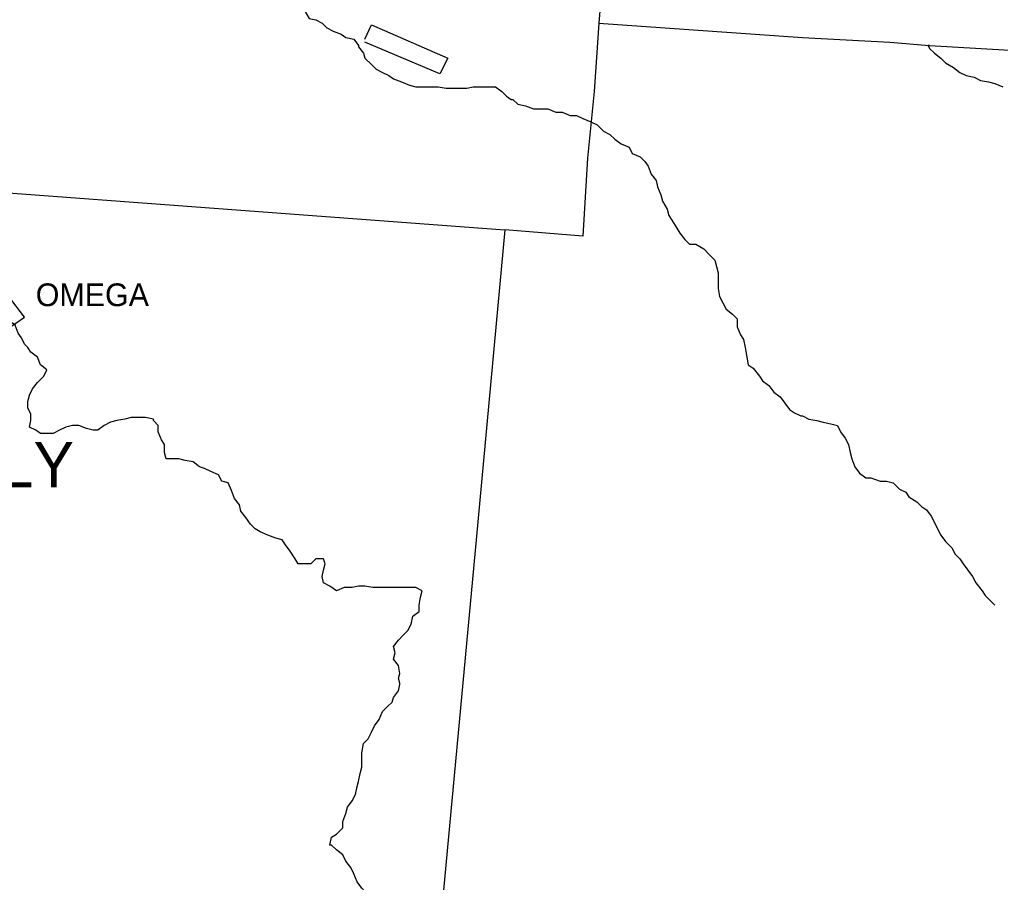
# Model space of a CAD drawing. Extents: x 0 to 34, y 0 to 22.
# Drawn here: x 6.387 to 7.227, y 17.766 to 18.506 of the extents above; entities that cross this region are included whole.
import ezdxf

# ---------------------------------------------------------------- set-up
doc = ezdxf.new("R2010")
doc.units = 0
doc.layers.add('Default', color=7, linetype='Continuous')

msp = doc.modelspace()

# ---------------------------------------------------------------- linework, layer by layer
at = {"layer": 'Default'}
for points in [[(6.94709, 19.42727), (6.93619, 19.25821), (6.91028, 18.871), (6.89937, 18.6992), (6.88301, 18.50287)], [(6.59533, 18.5465), (6.59942, 18.54105), (6.60487, 18.53832), (6.60897, 18.5315), (6.61169, 18.52741), (6.61715, 18.52741), (6.62124, 18.5206), (6.62533, 18.51651), (6.63078, 18.51378), (6.63487, 18.50696), (6.64032, 18.5056), (6.64578, 18.50287), (6.64987, 18.49878), (6.65532, 18.49605), (6.66214, 18.49333), (6.66623, 18.4906), (6.67305, 18.48924), (6.67714, 18.48378), (6.67714, 18.48242)], [(6.68259, 18.48924), (6.68804, 18.50151), (6.75349, 18.47288), (6.74667, 18.45924), (6.68259, 18.48651)], [(6.88301, 18.50287), (6.88301, 18.50287), (6.87892, 18.44424), (6.87347, 18.38698), (6.86938, 18.32017), (6.80257, 18.32563)], [(6.88301, 18.50287), (7.05753, 18.4906), (7.13252, 18.48651), (7.1666, 18.48378), (7.27977, 18.47697), (7.27431, 18.4197), (7.31249, 18.41561), (7.35339, 18.4088), (7.40929, 18.40062), (7.44065, 18.39925), (7.49792, 18.39925), (7.55109, 18.39925), (7.60017, 18.39107), (7.67925, 18.38016), (7.66698, 18.21383)], [(6.67714, 18.48242), (6.68123, 18.47697), (6.68259, 18.47288), (6.68804, 18.46742), (6.69213, 18.46333), (6.69759, 18.46061), (6.70304, 18.45788), (6.70713, 18.45515), (6.71395, 18.45243), (6.72077, 18.4497), (6.72622, 18.44833), (6.73167, 18.44833), (6.73849, 18.44833), (6.74531, 18.44833), (6.75212, 18.44697), (6.75621, 18.44697), (6.76303, 18.44697), (6.76985, 18.44697), (6.7753, 18.44833), (6.78076, 18.44833), (6.78894, 18.44833), (6.79439, 18.44833), (6.79984, 18.44424), (6.80393, 18.44015), (6.80802, 18.43743), (6.80939, 18.43743)], [(7.1666, 18.48378), (7.16524, 18.48378), (7.1666, 18.48106), (7.17069, 18.47697), (7.17615, 18.47288), (7.18024, 18.46879), (7.18706, 18.4647), (7.19251, 18.46061), (7.19796, 18.45788), (7.20478, 18.45652), (7.21023, 18.45379), (7.21705, 18.45243), (7.2225, 18.45106), (7.22932, 18.44833)], [(4.80243, 18.46879), (4.94014, 18.46061), (5.51141, 18.4197), (6.14268, 18.37471), (6.80257, 18.32563)], [(6.80939, 18.43743), (6.81348, 18.43334), (6.8203, 18.43197), (6.82711, 18.42925), (6.83257, 18.42925), (6.83938, 18.42925), (6.8462, 18.42652), (6.85165, 18.42652), (6.85847, 18.42379), (6.86392, 18.42379), (6.86938, 18.42107), (6.8762, 18.41834), (6.8762, 18.41834)], [(6.8762, 18.41834), (6.88165, 18.41561), (6.8871, 18.41016), (6.89256, 18.40743), (6.89665, 18.40334), (6.9021, 18.39925), (6.90892, 18.39652), (6.91164, 18.39107), (6.91846, 18.38834), (6.92255, 18.38425), (6.92528, 18.38016), (6.92801, 18.37335), (6.9321, 18.36789), (6.93346, 18.36244), (6.93619, 18.35562), (6.93755, 18.35017), (6.94164, 18.34335), (6.943, 18.3379), (6.94573, 18.33381), (6.94982, 18.32699), (6.95255, 18.3229), (6.95664, 18.31745), (6.96073, 18.31336), (6.96618, 18.31336), (6.96618, 18.31336)], [(6.80257, 18.32563), (6.77803, 18.05976), (6.74667, 17.72572), (6.75621, 17.72163), (6.74667, 17.60983), (6.72486, 17.3576), (6.72349, 17.32624)], [(6.96618, 18.31336), (6.973, 18.30927), (6.97709, 18.30518), (6.98254, 18.29972), (6.98391, 18.29427), (6.98527, 18.28881), (6.98527, 18.282), (6.98527, 18.27518), (6.98663, 18.26836), (6.98936, 18.26291), (6.99209, 18.25746), (6.99754, 18.25337), (7.00163, 18.24928), (7.00163, 18.24246), (7.00436, 18.23564), (7.00708, 18.23155), (7.00845, 18.22473), (7.00981, 18.21655), (7.01117, 18.20974), (7.01526, 18.20701), (7.02072, 18.20019), (7.02345, 18.1961), (7.0289, 18.19201), (7.03299, 18.18656), (7.03844, 18.18247), (7.04253, 18.17701), (7.04662, 18.17156), (7.05071, 18.16883), (7.05617, 18.16611), (7.05617, 18.16611), (7.05753, 18.16611)], [(6.37582, 18.26836), (6.34719, 18.24928), (6.36082, 18.23019), (6.39082, 18.25064), (6.37718, 18.26836)], [(6.39082, 18.22746), (6.38809, 18.23291), (6.38536, 18.237), (6.38264, 18.24382), (6.37718, 18.24791), (6.37718, 18.252), (6.37037, 18.25337), (6.36628, 18.24928), (6.36355, 18.252), (6.36082, 18.25746), (6.3581, 18.26018), (6.3581, 18.26155)], [(6.39627, 18.16747), (6.39354, 18.17292), (6.39354, 18.17838), (6.39491, 18.18383), (6.39763, 18.18928), (6.40173, 18.19474), (6.40718, 18.20019), (6.40991, 18.20565), (6.40445, 18.20974), (6.40173, 18.21655), (6.39627, 18.22064), (6.39354, 18.22473), (6.39082, 18.22746)], [(6.50125, 18.16338), (6.49444, 18.16474), (6.48762, 18.16474), (6.48217, 18.16474), (6.47671, 18.16338), (6.4699, 18.16202), (6.46444, 18.16065), (6.45899, 18.15793), (6.45354, 18.15384), (6.44944, 18.15384), (6.44399, 18.1552), (6.43717, 18.15793), (6.43172, 18.15793), (6.42627, 18.15656), (6.42081, 18.15384), (6.41536, 18.15111), (6.40991, 18.15111), (6.40445, 18.15111), (6.40036, 18.15384), (6.39491, 18.15656), (6.39627, 18.16202), (6.39627, 18.16611), (6.39627, 18.16747)], [(6.51216, 18.12929), (6.5108, 18.13475), (6.5108, 18.14157), (6.50807, 18.14566), (6.50535, 18.15247), (6.50535, 18.15793), (6.50125, 18.16202), (6.50125, 18.16202), (6.50125, 18.16338)], [(7.05753, 18.16611), (7.06298, 18.16338), (7.0698, 18.16202), (7.07526, 18.16065), (7.08207, 18.15929), (7.08753, 18.15793), (7.09025, 18.15247), (7.09434, 18.14702), (7.09707, 18.14157), (7.09843, 18.13475), (7.0998, 18.12929), (7.10252, 18.12248), (7.10661, 18.11702), (7.11207, 18.11293), (7.11616, 18.11293), (7.12434, 18.11021), (7.12979, 18.11021), (7.13525, 18.10884), (7.1407, 18.10339), (7.14615, 18.10066), (7.14888, 18.09657), (7.1557, 18.09248), (7.15979, 18.08839), (7.16388, 18.08566)], [(6.56806, 18.10203), (6.56534, 18.10884), (6.55988, 18.11021), (6.55716, 18.11566), (6.55034, 18.11839), (6.54488, 18.12111), (6.54079, 18.12248), (6.53534, 18.12657), (6.52852, 18.12793), (6.52307, 18.12929), (6.51625, 18.12929), (6.51353, 18.12929), (6.51216, 18.12929)], [(6.71259, 17.93705), (6.71122, 17.94114), (6.71259, 17.94523), (6.71122, 17.95205), (6.70713, 17.9575), (6.70849, 17.96296), (6.70713, 17.96841), (6.71122, 17.97386), (6.71531, 17.97795), (6.7194, 17.98204), (6.72213, 17.9875), (6.72349, 17.99432), (6.72895, 17.99841), (6.72895, 18.00386), (6.73031, 18.01068), (6.73167, 18.01613), (6.72622, 18.01886), (6.72077, 18.01886), (6.71259, 18.01886), (6.70713, 18.01886), (6.70031, 18.01886), (6.69486, 18.01886), (6.68941, 18.01886), (6.68259, 18.02022), (6.67714, 18.02022), (6.67168, 18.01886), (6.66487, 18.01886), (6.65805, 18.01613), (6.65259, 18.02022), (6.64714, 18.02295), (6.64578, 18.0284), (6.64714, 18.03385), (6.6485, 18.03931), (6.64714, 18.0434), (6.64032, 18.0434), (6.63623, 18.03931), (6.63078, 18.03931), (6.62533, 18.03931), (6.6226, 18.0434), (6.61851, 18.05022), (6.61442, 18.05567), (6.61169, 18.05976), (6.60624, 18.06112), (6.59942, 18.06385), (6.5926, 18.06658), (6.58851, 18.0693), (6.58442, 18.07339), (6.58033, 18.07885), (6.57624, 18.0843), (6.57488, 18.08976), (6.57079, 18.09521), (6.56806, 18.10203), (6.56806, 18.10203), (6.56806, 18.10203), (6.56806, 18.10203)], [(7.16388, 18.08566), (7.16797, 18.08021), (7.17069, 18.07476), (7.17342, 18.0693), (7.17615, 18.06385), (7.18024, 18.0584), (7.18569, 18.05294), (7.18842, 18.04749), (7.19251, 18.0434), (7.19524, 18.03931), (7.19933, 18.03385), (7.20342, 18.0284), (7.20614, 18.02295), (7.2116, 18.01613), (7.21432, 18.01204), (7.21978, 18.00659), (7.2225, 18.00386), (7.2225, 18.00386)], [(6.65259, 17.79798), (6.65396, 17.8048), (6.65805, 17.80753), (6.6635, 17.81298), (6.6635, 17.81843), (6.66623, 17.82525), (6.66759, 17.83071), (6.67168, 17.83616), (6.67441, 17.84161), (6.67577, 17.84843), (6.67714, 17.85252), (6.6785, 17.85934), (6.67986, 17.86479), (6.67986, 17.87161), (6.67986, 17.87706), (6.68123, 17.88524), (6.68532, 17.88933), (6.68804, 17.89479), (6.69077, 17.90024), (6.69486, 17.90569), (6.69759, 17.91251), (6.70168, 17.9166), (6.70577, 17.92069), (6.70713, 17.92478), (6.71122, 17.93023), (6.71259, 17.93569), (6.71259, 17.93705)], [(6.68532, 17.74481), (6.68532, 17.75299), (6.68259, 17.75844), (6.67986, 17.76117), (6.67577, 17.76662), (6.67305, 17.77344), (6.67032, 17.7789), (6.66623, 17.78435), (6.6635, 17.7898), (6.65805, 17.79389), (6.65396, 17.79798), (6.65259, 17.79798)]]:
    msp.add_lwpolyline(points, dxfattribs=at)

# ---------------------------------------------------------------- texts
for s, height, p in [('OMEGA', 0.019502, (6.40036, 18.26018)), ('WAVERLY', 0.039005, (6.17812, 18.10475))]:
    msp.add_text(s, height=height, dxfattribs=at).set_placement(p)

doc.saveas('drawing.dxf')
